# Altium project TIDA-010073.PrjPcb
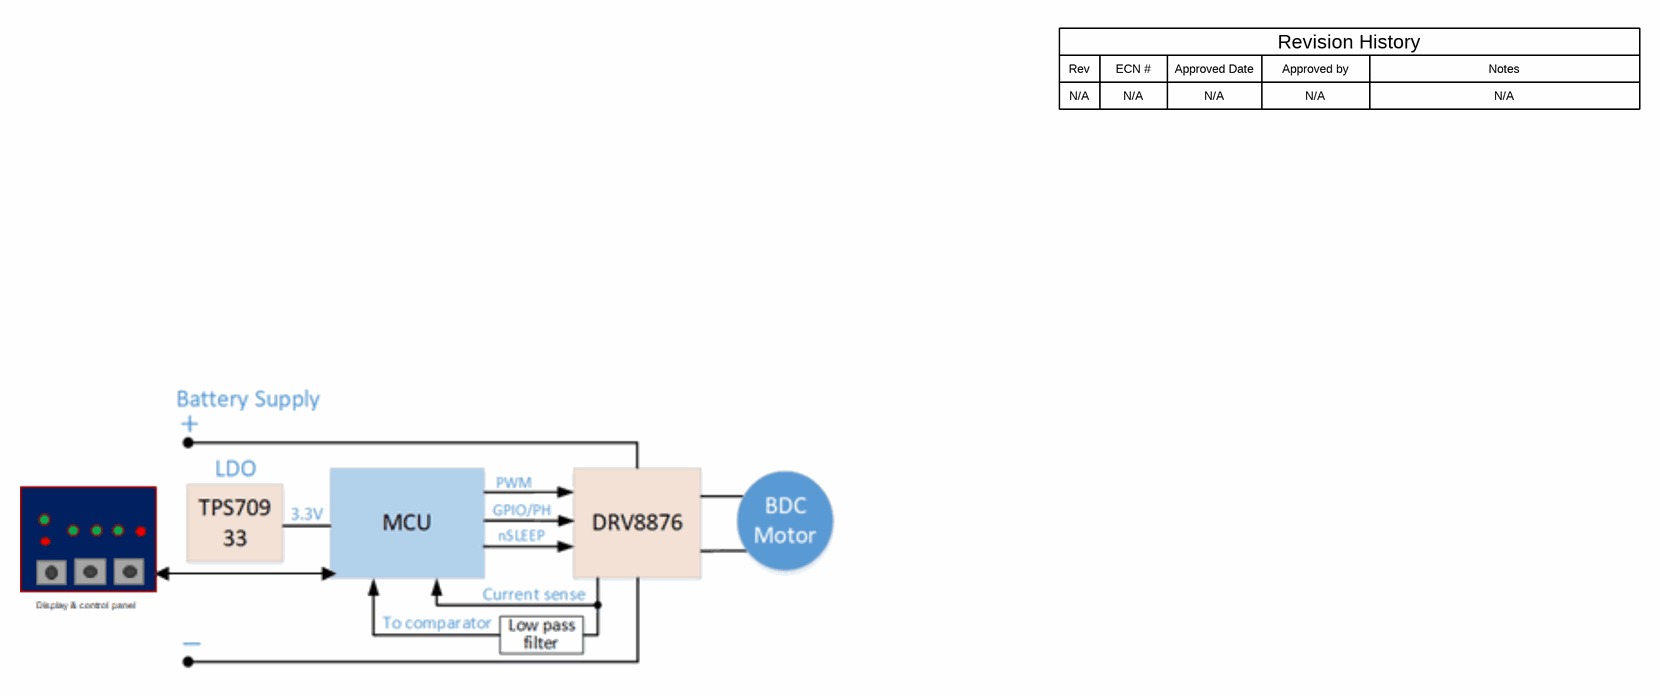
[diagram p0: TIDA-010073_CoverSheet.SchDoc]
TID: TIDA-010073; TechSupport: http://www.ti.com/support; SCH_Rev: E1; PRJ_Title: 18V_2A_25mm diameter brushed dc motor driver reference design; PRJ_Number: TIDA-010073; PRJ_Engineer: Hawken Li; PRJ_Customer: Public Release; PCB_Rev: E1; PCB_Layout: Hawken Li; CopyrightYear: 2017
3 sheets, 48 parts. Net scope: global (net labels, ports and power ports of the same name join across sheets).
Board file: TIDA-010073.PcbDoc
Sheets:
  TIDA-010073_CoverSheet.SchDoc
  TIDA-010073_Page1.SchDoc
  TIDA-010073_EVM_Hardware.SchDoc

## Sheet TIDA-010073_CoverSheet.SchDoc
size 431 x 279 mm; Date: Not shown in title block; ApprovedBy: Not shown in title block; CheckedBy: Not shown in title block; Author: Not shown in title block; CompanyName: Not shown in title block; Engineer: Not shown in title block; Organization: Not shown in title block; Address1: Not shown in title block; Address2: Not shown in title block; Address3: Not shown in title block; Address4: Not shown in title block; DocumentNumber: 1; Revision: Use project parameter SCH_Rev; SheetNumber: 1; SheetTotal: 3; PageSetup: Record=PageOptions¦CenterHorizontal=True¦CenterVertical=True¦PrintScale=1.00¦XCorrection=1.00¦YCorrection=1.00¦PrintKind=0¦BorderSize=5000000¦LeftOffset=0¦BottomOffset=0¦Orientation=2¦PaperLength=1000¦PaperWidth=1000¦Scale=100¦PaperSource=15¦PrintQuality=600¦MediaType=1¦DitherType=10¦PaperKind=Letter¦PrintScaleMode=1

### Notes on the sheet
- Rev
- N/A
- ECN #
- Approved Date
- Approved by
- Revision History
- Notes

## Sheet TIDA-010073_Page1.SchDoc
size 431 x 279 mm; Date: Not shown in title block; ApprovedBy: Not shown in title block; CheckedBy: Not shown in title block; Author: Not shown in title block; CompanyName: Not shown in title block; Engineer: Not shown in title block; Organization: Not shown in title block; Address1: Not shown in title block; Address2: Not shown in title block; Address3: Not shown in title block; Address4: Not shown in title block; DocumentNumber: 1; Revision: Use project parameter SCH_Rev; SheetNumber: 2; SheetTotal: 3; PageSetup: Record=PageOptions¦CenterHorizontal=True¦CenterVertical=True¦PrintScale=1.00¦XCorrection=1.00¦YCorrection=1.00¦PrintKind=0¦BorderSize=5000000¦LeftOffset=0¦BottomOffset=0¦Orientation=2¦PaperLength=1000¦PaperWidth=1000¦Scale=100¦PaperSource=15¦PrintQuality=600¦MediaType=1¦DitherType=10¦PaperKind=Letter¦PrintScaleMode=1
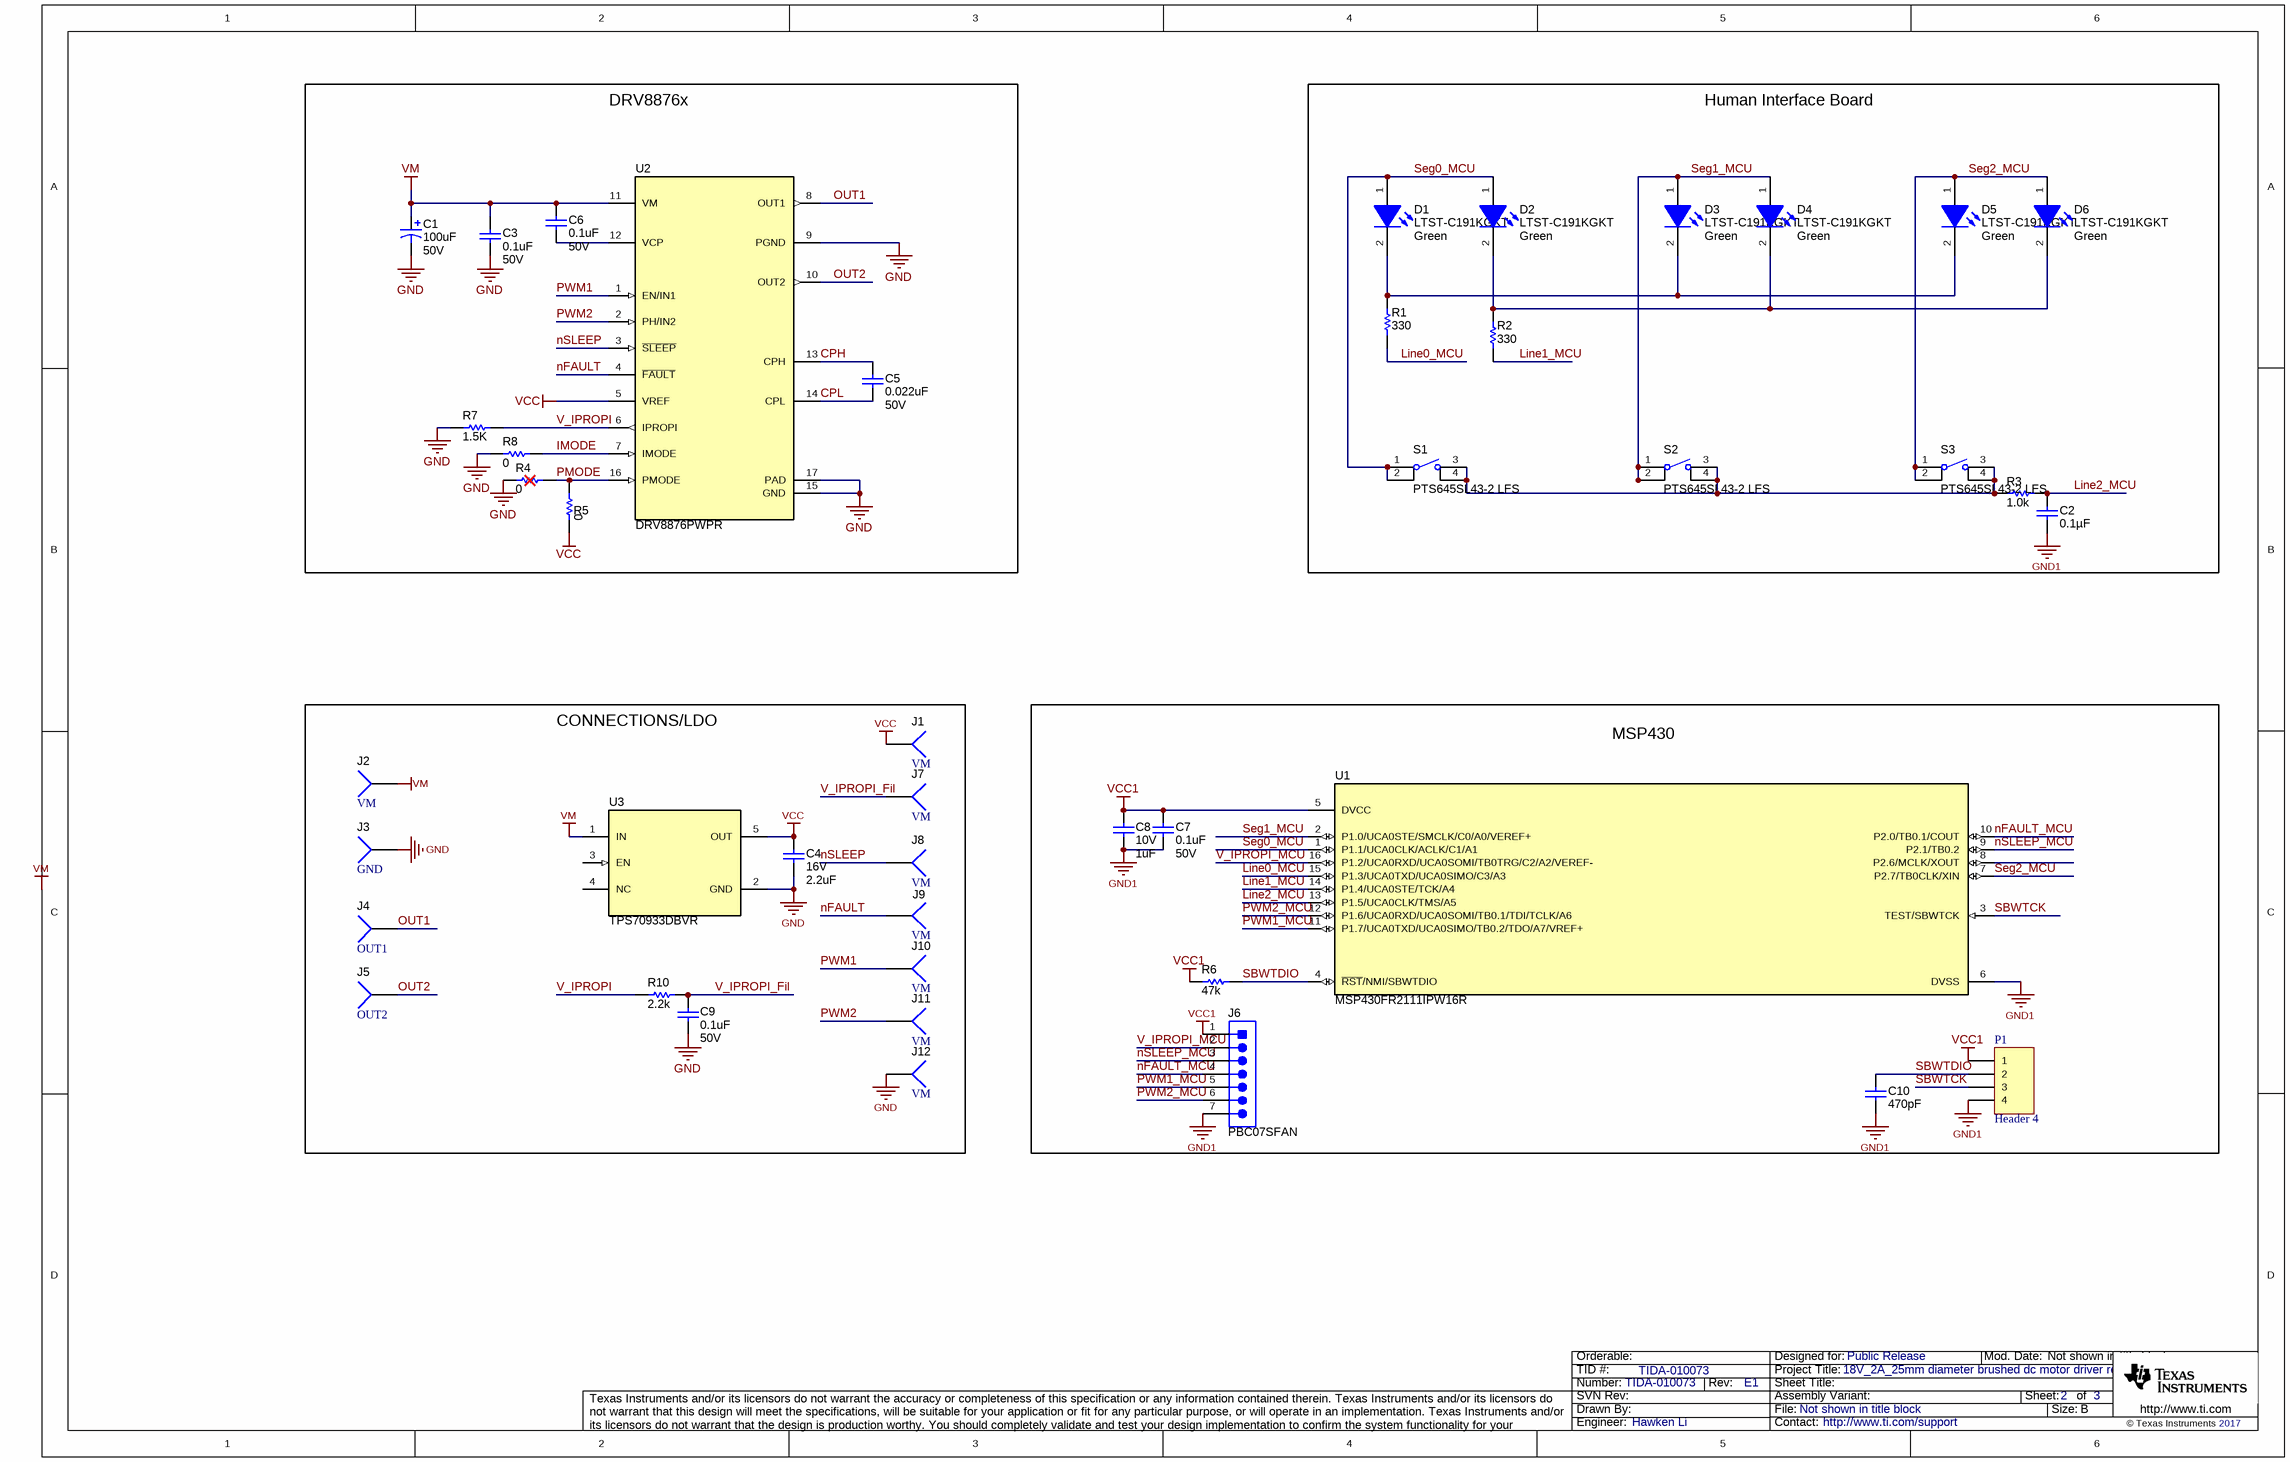
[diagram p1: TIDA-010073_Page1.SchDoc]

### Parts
C1  ValueDisplayed: 100uF  VDC_V: 50V  [BT_1000x1250]  (hidden comment: UBT1H101MPD1TD)
C2  ValueDisplayed: 0.1µF  [0603L]  (hidden comment: C0603X104K8RACTU)
C3  ValueDisplayed: 0.1uF  VDC_V: 50V  [0603L]  (hidden comment: C1608X7R1H104K080AA)
C4  VDC_V: 16V  ValueDisplayed: 2.2uF  [0603]  (hidden comment: CGA3E1X7S1C225M080AC)
C5  ValueDisplayed: 0.022uF  VDC_V: 50V  [0603L]  (hidden comment: 885012206091)
C6  ValueDisplayed: 0.1uF  VDC_V: 50V  [0603L]  (hidden comment: C1608X7R1H104K080AA)
C7  ValueDisplayed: 0.1uF  VDC_V: 50V  [0603L]  (hidden comment: C1608X7R1H104K080AA)
C8  VDC_V: 10V  ValueDisplayed: 1uF  [0603L]  (hidden comment: 885012206026)
C9  ValueDisplayed: 0.1uF  VDC_V: 50V  [0603L]  (hidden comment: C1608X7R1H104K080AA)
C10  ValueDisplayed: 470pF  [0603L]  (hidden comment: C0603C471K5RACTU)
D1  LTST-C191KGKT  value Green  [LTST-C191_Green]
D2  LTST-C191KGKT  value Green  [LTST-C191_Green]
D3  LTST-C191KGKT  value Green  [LTST-C191_Green]
D4  LTST-C191KGKT  value Green  [LTST-C191_Green]
D5  LTST-C191KGKT  value Green  [LTST-C191_Green]
D6  LTST-C191KGKT  value Green  [LTST-C191_Green]
J1  VM  [PIN1]
J2  VM  [PIN1]
J3  GND  [PIN1]
J4  OUT1  [PIN1]
J5  OUT2  [PIN1]
J6  PBC07SFAN  [Sullins_xxC07SFAN]
J7  VM  [PIN1]
J8  VM  [PIN1]
J9  VM  [PIN1]
J10  VM  [PIN1]
J11  VM  [PIN1]
J12  VM  [PIN1]
P1  Header 4  [HDR1X4]
R1  ValueDisplayed: 330  [0603]  (hidden comment: RC0603JR-07330RL)
R2  ValueDisplayed: 330  [0603]  (hidden comment: RC0603JR-07330RL)
R3  ValueDisplayed: 1.0k  [0603]  (hidden comment: RC0603JR-071KL)
R4  ValueDisplayed: 0  [0603L]  (hidden comment: ERJ-3GEY0R00V)
R5  ValueDisplayed: 0  [0603L]  (hidden comment: ERJ-3GEY0R00V)
R6  ValueDisplayed: 47k  [0603]  (hidden comment: RC0603JR-0747KL)
R7  ValueDisplayed: 1.5K  [0603L]  (hidden comment: ERJ-3GEY0R00V)
R8  ValueDisplayed: 0  [0603L]  (hidden comment: ERJ-3GEY0R00V)
R10  ValueDisplayed: 2.2k  [0603L]  (hidden comment: RC0603JR-072K2L)
S1  PTS645SL43-2 LFS  [SW_PTS645SL43-2]
S2  PTS645SL43-2 LFS  [SW_PTS645SL43-2]
S3  PTS645SL43-2 LFS  [SW_PTS645SL43-2]
U1  MSP430FR2111IPW16R  [PW0016A_L]
U2  DRV8876PWPR  [PWP0016J_N]
U3  TPS70933DBVR  [DBV0005A_N]

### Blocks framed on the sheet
DRV8876x: C1 C3 C5 C6 R4 R5 R7 R8 U2
Human Interface Board: C2 D1-D6 R1-R3 S1-S3
CONNECTIONS/LDO: C4 C9 J1-J5 J7-J12 R10 U3
MSP430: C7 C8 C10 J6 P1 R6 U1

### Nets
GND: C1.2(-) C3.2 C4.2 C9.2 J3.1 J12.1 R4.1 R7.1 R8.1 U2.9(PGND) U2.15(GND) U2.17(PAD) U3.2(GND)
GND1: C2.2 C7.2 C8.2 C10.2 J6.7 P1.4 U1.6(DVSS)
VCC: C4.1 J1.1 R5.1 U2.5(VREF) U3.5(OUT)
VCC1: C7.1 C8.1 J6.1 P1.1 R6.1 U1.5(DVCC)
VM: C1.1(+) C3.1 C6.1 J2.1 U2.11(VM) U3.1(IN)
CPH: C5.1 U2.13(CPH)
CPL: C5.2 U2.14(CPL)
IMODE: R8.2 U2.7(IMODE)
Line0_MCU: R1.1 U1.15(P1.3/UCA0TXD/UCA0SIMO/C3/A3)
Line1_MCU: R2.1 U1.14(P1.4/UCA0STE/TCK/A4)
Line2_MCU: C2.1 R3.2 U1.13(P1.5/UCA0CLK/TMS/A5)
nFAULT: J9.1 U2.4(~{FAULT})
nFAULT_MCU: J6.4 U1.10(P2.0/TB0.1/COUT)
nSLEEP: J8.1 U2.3(~{SLEEP})
nSLEEP_MCU: J6.3 U1.9(P2.1/TB0.2)
OUT1: J4.1 U2.8(OUT1)
OUT2: J5.1 U2.10(OUT2)
PMODE: R4.2 R5.2 U2.16(PMODE)
PWM1: J10.1 U2.1(EN/IN1)
PWM1_MCU: J6.5 U1.11(P1.7/UCA0TXD/UCA0SIMO/TB0.2/TDO/A7/VREF+)
PWM2: J11.1 U2.2(PH/IN2)
PWM2_MCU: J6.6 U1.12(P1.6/UCA0RXD/UCA0SOMI/TB0.1/TDI/TCLK/A6)
SBWTCK: P1.3 U1.3(TEST/SBWTCK)
SBWTDIO: C10.1 P1.2 R6.2 U1.4(~{RST}/NMI/SBWTDIO)
Seg0_MCU: D1.1(A) D2.1(A) S1.1 S1.2 U1.1(P1.1/UCA0CLK/ACLK/C1/A1)
Seg1_MCU: D3.1(A) D4.1(A) S2.1 S2.2 U1.2(P1.0/UCA0STE/SMCLK/C0/A0/VEREF+)
Seg2_MCU: D5.1(A) D6.1(A) S3.1 S3.2 U1.7(P2.7/TB0CLK/XIN)
V_IPROPI: R7.2 R10.1 U2.6(IPROPI)
V_IPROPI_Fil: C9.1 J7.1 R10.2
V_IPROPI_MCU: J6.2 U1.16(P1.2/UCA0RXD/UCA0SOMI/TB0TRG/C2/A2/VEREF-)
NetC6_2: C6.2 U2.12(VCP)
NetD1_2: D1.2(K) D3.2(K) D5.2(K) R1.2
NetD2_2: D2.2(K) D4.2(K) D6.2(K) R2.2
NetR3_1: R3.1 S1.3 S1.4 S2.3 S2.4 S3.3 S3.4

Not connected (* = marked no-connect by the designer): U1 8(P2.6/MCLK/XOUT); U3 3(EN) 4(NC)

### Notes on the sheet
- Labels drawn without touching a wire or pin: VM

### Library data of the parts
C1 = CMP-0009918-2: CAP, AL, 100 uF, 50 V, +/- 20%, TH; Manufacturer: Nichicon; Polarized: Y; CompType: Capacitor; Value: 100uF; U/M: EA; Cap_F: 100µF; Value1: Unknown; IRMS_A: 5.55dA; TaMin_C: -40°C; TaMax_C: 125°C; Cap_Case: 10x12.5mm; SizeAreaWB_mm2: 144; SizeArea_mm2: 100; SizeX_mm: 10; SizeZ_mm: 14.5; AEC Category: Q200; AEC Qualified: N
C2 = C0603X104K8RACTU: CAP, CERM, 0.1 µF, 10 V,+/- 10%, X7R, 0603; Manufacturer: Kemet; Polarized: N; CompType: Capacitor; Value: 0.1uF; U/M: EA; Cap_F: 0.0000001; Tolerance_%: 10; Value2: 10V; TaMin_C: -55; TaMax_C: 125; Cap_Case: 0603; SizeArea_mm2: 1.28; SizeAreaWB_mm2: 4.68; SizeX_mm: 1.6; SizeY_mm: 0.8; SizeZ_mm: 1; AEC Category: Q200; Green_Lifecycle: Not Set; Green_REACh: Incomplete
C3 C6 C7 C9 = CMP-0007044-5: CAP, CERM, 0.1 uF, 50 V, +/- 10%, X7R, 0603; Manufacturer: TDK; Polarized: N; CompType: Capacitor; Value: 0.1uF; U/M: EA; Cap_F: 100nF; ESR_ohm: 0.0296; Value1: 0.0296 ohm; IRMS_A: 9.7199dA; TaMin_C: -55°C; TaMax_C: 125°C; Cap_Case: 0603; SizeArea_mm2: 1.28; SizeAreaWB_mm2: 4.68; SizeX_mm: 1.6; SizeY_mm: 0.8; SizeZ_mm: 1; AEC Category: Q200
C4 = CMP-0007068-4: CAP, CERM, 2.2 uF, 16 V, +/- 20%, X7S, AEC-Q200 Grade 1, 0603; Manufacturer: TDK; TaMin_C: -55°C; Polarized: N; SizeAreaWB_mm2: 4.68; Value1: Unknown; U/M: EA; Value: 2.2uF; TaMax_C: 125°C; SizeZ_mm: 1; SizeX_mm: 1.6; SizeY_mm: 0.8; SizeArea_mm2: 1.28; AEC Qualified: Y; Cap_F: 2.2µF; AEC Category: Q200
C5 = CMP-0006836-4: CAP, CERM, 0.022 uF, 50 V, +/- 10%, X7R, 0603; Manufacturer: Wurth Elektronik; Polarized: N; U/M: EA; Cap_F: 22nF; Value1: Unknown; TaMin_C: -55°C; TaMax_C: 125°C; Cap_Case: 0603; SizeArea_mm2: 1.28; SizeAreaWB_mm2: 4.68; SizeX_mm: 1.6; SizeY_mm: 0.8; SizeZ_mm: 1; AEC Category: Q200
C8 = CMP-0064932-4: CAP, CERM, 1 uF, 10 V,+/- 10%, X7R, 0603; Manufacturer: Wurth Elektronik; TaMin_C: -55°C; Polarized: N; SizeAreaWB_mm2: 4.68; Value1: Unknown; U/M: EA; Value: 1uF; TaMax_C: 125°C; SizeZ_mm: 1; SizeX_mm: 1.6; SizeY_mm: 0.8; Cap_Case: 0603; SizeArea_mm2: 1.28; CompType: Capacitor; Cap_F: 1µF; AEC Category: Q200
C10 = C0603C471K5RACTU: CAP, CERM, 470 pF, 50 V,+/- 10%, X7R, 0603; Manufacturer: Kemet; Polarized: N; CompType: Capacitor; Value: 470pF; U/M: EA; Cap_F: 0.00000000047; Tolerance_%: 10; VDC_V: 50; Value2: 50V; TaMin_C: -55; TaMax_C: 125; Cap_Case: 0603; SizeArea_mm2: 1.28; SizeAreaWB_mm2: 4.68; SizeX_mm: 1.6; SizeY_mm: 0.8; SizeZ_mm: 1; AEC Category: Q200; Green_Lifecycle: Active; Green_REACh: Passed
D1-D6 = CMP-0078478-2: LED, Green, SMD; Manufacturer: Lite-On; Value2: 2V; Vr_V: 5V; Ir_A: 10µA; Value1: 0.075W; Tjmax_C: 85°C; Green_Lifecycle: Not Set; Angle: 130; Type: AlInGaP; Power_TotalModule: 75mW; Io_A: 30mA; Green_REACh: Incomplete
J1-J5 J7-J12 = Socket
J6 = CMP-0054600-1: Header, 2.54 mm, Gold, 7x1, TH; Manufacturer: Sullins Connector Solutions; CNHeader: TRUE; Current_A: 3A; Gender: Male; Voltage_V: 1.8kV; Row_Count: 1; Pitch_mm: 2.54; CT: FALSE; Cert_UL: Y
P1 = Header 4: Header, 4-Pin
R1 R2 = CMP-0025912-5: RES, 330, 5%, 0.1 W, 0603; Manufacturer: Yageo; Power_W: 100mW; TempCo: 100 ppm/C; Value_Code: 330R; Value: 330; EIA_Code: E24; SizeX_mm: 1.6; SizeY_mm: 0.8; SizeZ_mm: 1; Value2: 0.1W; SizeArea_mm2: 1.28; AEC Qualified: N; VDC_V: 75V; AEC Category: Q200; SizeAreaWB_mm2: 4.68
R3 = CMP-0025899-5: RES, 1.0 k, 5%, 0.1 W, 0603; Manufacturer: Yageo; Power_W: 100mW; TempCo: 100 ppm/C; Value_Code: 1k00; Value: 1.0k; EIA_Code: E24; Res_ohm: 1k; SizeX_mm: 1.6; SizeY_mm: 0.8; SizeZ_mm: 1; Value2: 0.1W; SizeArea_mm2: 1.28; CompType: Resistor; AEC Qualified: N; VDC_V: 75V; AEC Category: Q200; SizeAreaWB_mm2: 4.68
R4 R5 R7 R8 = CMP-0025874-3: RES, 0, 5%, 0.1 W, 0603; Manufacturer: Panasonic; Value: 0; Value_Code: 0000; Power_W: 100mW; Value2: 0.1W; VDC_V: 50V; TempCo: 600 ppm/C; EIA_Code: E24; U/M: EA; SizeArea_mm2: 1.28; SizeX_mm: 1.6; SizeY_mm: 0.8; SizeZ_mm: 1; AEC Category: Q200
R6 = CMP-0025925-5: RES, 47 k, 5%, 0.1 W, 0603; Manufacturer: Yageo; Power_W: 100mW; TempCo: 100 ppm/C; Value_Code: 47k0; Value: 47k; EIA_Code: E24; SizeX_mm: 1.6; SizeY_mm: 0.8; SizeZ_mm: 1; Value2: 0.1W; SizeArea_mm2: 1.28; AEC Qualified: N; VDC_V: 75V; AEC Category: Q200; SizeAreaWB_mm2: 4.68
R10 = RC0603JR-072K2L: RES, 2.2 k, 5%, 0.1 W, 0603; Manufacturer: Yageo America; CompType: Resistor; Value: 2.2k; Res_ohm: 2200; Value_Code: 2k20; Tolerance_%: 5; Power_W: 0.1; Value2: 0.1W; VDC_V: 50; TempCo: 100 ppm/C; SizeArea_mm2: 1.28; SizeX_mm: 1.6; SizeY_mm: 0.8; SizeZ_mm: 1; EIA_Code: E24; U/M: EA; AEC Category: Q200; Green_Lifecycle: Active; Green_REACh: Passed
S1-S3 = CMP-0085821-1: Switch, SPST-NO, 0.05 A, 12 VDC, TH; Manufacturer: C&K Components; SizeY_mm: 6; CurrentRating_mA: 50A; SizeZ_mm: 4.4; SizeArea_mm2: 47.4; VDC_V: 12V; PositionCount: 1; SizeX_mm: 7.9; SizeAreaWB_mm2: 79.2; SwitchFunction: Off-Mom
U1 = CMP-0076600-1: 16 MHz Ultra-Low-Power Microcontroller With 4 KB FRAM, 1 KB SRAM, 12 IO, 8 ch ADC10, PW0016A (TSSOP-16); Manufacturer: Texas Instruments; SizeAreaWB_mm2: 58.8; SizeArea_mm2: 32.0; SizeZ_mm: 1.2; SizeY_mm: 5.0; U/M: EA; CompType: IC; SizeX_mm: 6.4
U2 = CMP-0079885-2: H-Bridge Motor Drivers With Integrated Current Sense and Regulation, PWP0016J (TSSOP-16); Alternate Manufacturer: Texas Instruments; SizeAreaWB_mm2: 58.8; SizeZ_mm: 1.2; SizeX_mm: 6.4; SizeY_mm: 5; SizeArea_mm2: 32; CompType: IC; AEC Qualified: N; AEC Category: Q200
U3 = CMP-0073793-1: 150-mA, 30-V, Ultra-Low IQ, Wide Input Low-Dropout Regulator with Reverse Current Protection, DBV0005A (SOT-23-5); Alternate PartNumber: TPS70933DBVT; Alternate Manufacturer: Texas Instruments; Green_Lifecycle: Active; SizeAreaWB_mm2: 14.82; Green_REACh: Passed; U/M: EA; SizeZ_mm: 1.45; SizeX_mm: 2.8; SizeY_mm: 2.9; SizeArea_mm2: 8.12; CompType: IC

## Sheet TIDA-010073_EVM_Hardware.SchDoc
size 431 x 279 mm; Date: Not shown in title block; ApprovedBy: Not shown in title block; CheckedBy: Not shown in title block; Author: Not shown in title block; CompanyName: Not shown in title block; Engineer: Not shown in title block; Organization: Not shown in title block; Address1: Not shown in title block; Address2: Not shown in title block; Address3: Not shown in title block; Address4: Not shown in title block; DocumentNumber: 1; Revision: Use project parameter SCH_Rev; SheetNumber: 3; SheetTotal: 3; PageSetup: Record=PageOptions¦CenterHorizontal=True¦CenterVertical=True¦PrintScale=1.00¦XCorrection=1.00¦YCorrection=1.00¦PrintKind=0¦BorderSize=5000000¦LeftOffset=0¦BottomOffset=0¦Orientation=2¦PaperLength=1000¦PaperWidth=1000¦Scale=100¦PaperSource=15¦PrintQuality=600¦MediaType=1¦DitherType=10¦PaperKind=Letter¦PrintScaleMode=1
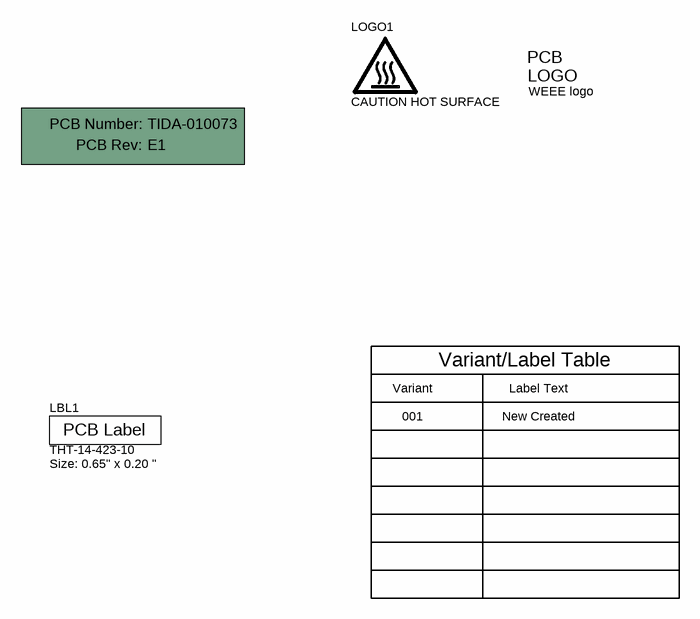
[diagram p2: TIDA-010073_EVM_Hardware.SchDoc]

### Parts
!PCB  Printed Circuit Board  (value not drawn)  (mechanical)
LBL1  THT-14-423-10  Note: Size: 0.65" x 0.20 "  [Label_650x200]
LOGO1  CAUTION HOT SURFACE  [IEC_HotSurface_Small]  (no BOM)
Logo4  WEEE logo  [WEEE_Minimum]  (no BOM)

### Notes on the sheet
- Variant
- Variant/Label Table
- Label Text
- 001
- New Created

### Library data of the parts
!PCB = CMP-0003618-2: Manufacturer: Any; PartNumber: TIDA-010073
LBL1 = CMP-0003625-1: Thermal Transfer Printable Labels, 0.650" W x 0.200" H - 10,000 per roll; Manufacturer: Brady; CompType: Label
LOGO1 = CMP-0074837-1: IEC 61010-1 Hot Surface Warning; Library Reference: IEC_HotSurface; SymbolCreator: a0412235
Logo4 = CMP-0074769-1

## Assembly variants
001: not fitted FID1 FID2 FID3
